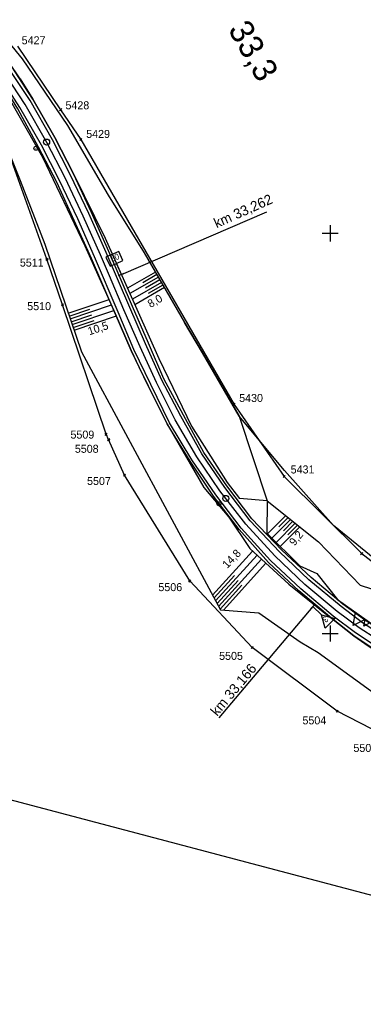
# Model space of a CAD drawing. Extents: x -805011 to -803920, y -1150790 to -1150234.
# Drawn here: x -804177.7 to -804091.7, y -1150790.1 to -1150546.6 of the extents above; entities that cross this region are included whole.
import ezdxf

# ---------------------------------------------------------------- set-up
doc = ezdxf.new("R2010")
doc.units = 0
for name, color, linetype in [('0381KM032-037P - Vrstva 1', 7, 'Continuous'), ('0381KM032-037P - Vrstva 17', 7, 'Continuous'), ('0381KM032-037P - Vrstva 4', 7, 'Continuous'), ('0381KM032-037P - Vrstva 48', 7, 'Continuous'), ('0381KM032-037P - Vrstva 49', 7, 'Continuous'), ('0381KM032-037P - Vrstva 5', 7, 'Continuous'), ('0381KM032-037P - Vrstva 50', 7, 'Continuous'), ('0381KM032-037P - Vrstva 7', 7, 'Continuous'), ('formát', 7, 'Continuous'), ('krizky_1000 - Vrstva 1', 7, 'Continuous'), ('szdc - hran DP', 7, 'Continuous'), ('szdc - szdc_cislo', 7, 'Continuous'), ('szdc - szdc_krizek', 7, 'Continuous')]:
    doc.layers.add(name, color=color, linetype=linetype)

msp = doc.modelspace()

# ---------------------------------------------------------------- linework, layer by layer
at = {"layer": '0381KM032-037P - Vrstva 1'}
for points in [[(-804170.82, -1150577.3), (-804176.26, -1150567.85), (-804182.37, -1150558.45), (-804188.8, -1150549.63), (-804195.8, -1150541.09), (-804203.2, -1150532.98), (-804210.73, -1150525.57), (-804219.76, -1150517.68), (-804222.98, -1150515.09)], [(-804121.06, -1150672.62), (-804127.59, -1150664.31), (-804133.36, -1150655.8), (-804138.71, -1150646.59), (-804143.42, -1150637.27), (-804147.52, -1150628.35), (-804151.54, -1150619.12), (-804155.16, -1150610.64), (-804157.42, -1150605.4), (-804161.72, -1150595.74), (-804166.25, -1150586.16), (-804170.82, -1150577.3)], [(-803978.41, -1150722.71), (-803983.51, -1150723.68), (-803993.92, -1150724.91), (-804004.46, -1150725.42), (-804014.95, -1150725.21), (-804025.47, -1150724.25), (-804035.41, -1150722.67), (-804044.08, -1150720.74), (-804054.77, -1150717.61), (-804064.47, -1150714.03), (-804074.16, -1150709.61), (-804083.95, -1150704.25), (-804092.73, -1150698.52), (-804098.22, -1150694.46), (-804106.33, -1150687.73), (-804113.82, -1150680.6), (-804121.06, -1150672.62)]]:
    msp.add_lwpolyline(points, dxfattribs=at)
at = {"layer": '0381KM032-037P - Vrstva 17'}
for points in [[(-804099.12, -1150672.95), (-804111.38, -1150659.24), (-804122.71, -1150645.64), (-804131.91, -1150629.82), (-804136.37, -1150622.31)], [(-804059.54, -1150698.86), (-804062.04, -1150700.07), (-804077.59, -1150690.55), (-804099.12, -1150672.95)]]:
    msp.add_lwpolyline(points, dxfattribs=at)
at = {"layer": '0381KM032-037P - Vrstva 4'}
for points in [[(-804155.96, -1150604.81), (-804160.35, -1150595.07), (-804164.87, -1150585.5), (-804169.43, -1150576.62), (-804175.01, -1150566.82), (-804181.12, -1150557.55), (-804187.68, -1150548.56)], [(-804155.31, -1150604.52), (-804159.65, -1150594.76), (-804164.13, -1150585.17), (-804168.86, -1150576.08), (-804174.28, -1150566.45), (-804180.44, -1150557.11), (-804187.11, -1150547.91)], [(-804159.67, -1150606.25), (-804163.99, -1150596.78), (-804168.29, -1150587.2), (-804172.88, -1150578.5), (-804178.08, -1150568.91), (-804181.43, -1150563.5), (-804184.18, -1150559.55), (-804190.46, -1150550.87)], [(-804158.94, -1150605.89), (-804163.07, -1150596.41), (-804167.66, -1150586.77), (-804172.11, -1150577.99), (-804177.55, -1150568.56), (-804183.56, -1150559.32), (-804190.06, -1150550.44)], [(-804132.06, -1150655.06), (-804137.36, -1150645.71), (-804142.06, -1150636.68), (-804146.12, -1150627.62), (-804150.08, -1150618.55), (-804155.96, -1150604.81)], [(-804131.6, -1150654.76), (-804136.67, -1150645.43), (-804141.53, -1150636.36), (-804145.41, -1150627.43), (-804149.44, -1150618.25), (-804155.31, -1150604.52)], [(-804135, -1150656.89), (-804140.73, -1150647.62), (-804145.48, -1150638.07), (-804149.71, -1150629.27), (-804153.71, -1150619.99), (-804159.67, -1150606.25)], [(-804134.56, -1150656.61), (-804140.15, -1150647.32), (-804144.81, -1150637.78), (-804149.09, -1150628.99), (-804152.99, -1150619.67), (-804158.94, -1150605.89)], [(-804073.38, -1150708.29), (-804083.27, -1150702.88), (-804091.89, -1150697.28), (-804097.27, -1150693.2), (-804105.34, -1150686.53), (-804112.64, -1150679.57), (-804120.03, -1150671.79), (-804126.35, -1150663.48), (-804132.06, -1150655.06)], [(-804073.1, -1150707.59), (-804077.68, -1150705.14), (-804082.78, -1150702.25), (-804091.44, -1150696.56), (-804096.83, -1150692.65), (-804104.73, -1150685.98), (-804112.1, -1150679.17), (-804119.6, -1150671.34), (-804125.86, -1150663.1), (-804131.6, -1150654.76)], [(-804075.18, -1150711.95), (-804085.34, -1150706.36), (-804094.07, -1150700.58), (-804099.68, -1150696.17), (-804107.82, -1150689.29), (-804115.4, -1150682.25), (-804122.72, -1150674.01), (-804129.15, -1150665.64), (-804135, -1150656.89)], [(-804074.79, -1150711.15), (-804084.84, -1150705.62), (-804093.69, -1150699.81), (-804099.23, -1150695.65), (-804107.33, -1150688.8), (-804114.94, -1150681.73), (-804122.23, -1150673.64), (-804128.61, -1150665.3), (-804134.56, -1150656.61)]]:
    msp.add_lwpolyline(points, dxfattribs=at)
at = {"layer": '0381KM032-037P - Vrstva 48'}
for p, q in [((-804143.67, -1150609.66), (-804150.65, -1150613.69)), ((-804142.92, -1150610.96), (-804150.03, -1150615.07)), ((-804142.17, -1150612.26), (-804149.42, -1150616.44)), ((-804143.3, -1150610.31), (-804146.82, -1150612.35)), ((-804142.55, -1150611.61), (-804146.14, -1150613.68)), ((-804141.42, -1150613.56), (-804148.81, -1150617.82)), ((-804141.8, -1150612.91), (-804145.46, -1150615.02)), ((-804165.46, -1150619.97), (-804155.27, -1150616.52)), ((-804165.22, -1150620.68), (-804160.09, -1150618.94)), ((-804164.98, -1150621.39), (-804154.65, -1150617.89)), ((-804164.5, -1150622.81), (-804154.04, -1150619.27)), ((-804164.74, -1150622.1), (-804159.54, -1150620.34)), ((-804164.26, -1150623.52), (-804158.99, -1150621.74)), ((-804164.02, -1150624.23), (-804153.43, -1150620.64)), ((-804111.08, -1150670.5), (-804115.64, -1150675.08)), ((-804109.9, -1150671.45), (-804114.57, -1150676.14)), ((-804108.72, -1150672.39), (-804113.51, -1150677.2)), ((-804110.49, -1150670.98), (-804112.8, -1150673.29)), ((-804109.31, -1150671.92), (-804111.68, -1150674.29)), ((-804108.13, -1150672.86), (-804110.56, -1150675.3)), ((-804107.54, -1150673.33), (-804112.45, -1150678.26)), ((-804129.38, -1150690.39), (-804119.38, -1150679.38)), ((-804128.63, -1150691.79), (-804118.27, -1150680.39)), ((-804127.87, -1150693.19), (-804117.16, -1150681.39)), ((-804126.68, -1150694.11), (-804116.05, -1150682.4)), ((-804129.01, -1150691.09), (-804123.91, -1150685.49)), ((-804128.25, -1150692.49), (-804122.98, -1150686.69)), ((-804127.5, -1150693.89), (-804122.05, -1150687.9))]:
    msp.add_line(p, q, dxfattribs=at)
at = {"layer": '0381KM032-037P - Vrstva 49'}
for q in [(-804122.66, -1150666.25), (-804115.86, -1150674.86)]:
    msp.add_line((-804115.71, -1150666.79), q, dxfattribs=at)
for points in [[(-804216.26, -1150515.03), (-804196.49, -1150533.54), (-804188.66, -1150542.31), (-804183.72, -1150548.22), (-804177, -1150556.4), (-804165.66, -1150573.06), (-804155.49, -1150590.5), (-804146.45, -1150604.86), (-804136.37, -1150622.31), (-804131.91, -1150629.82), (-804122.71, -1150645.64), (-804115.71, -1150666.79), (-804102.89, -1150677.06), (-804092.51, -1150687.92), (-804076.71, -1150692.97), (-804062.72, -1150701.97), (-804052.08, -1150706.52)], [(-804177.46, -1150561.39), (-804180.44, -1150557.11), (-804187.34, -1150547.5), (-804194.06, -1150539.52)], [(-804190.46, -1150550.87), (-804184.18, -1150559.55), (-804171.89, -1150581.01)], [(-804191.88, -1150555.68), (-804187.09, -1150562.15), (-804183.47, -1150572.06), (-804177.47, -1150586.83), (-804171.32, -1150602.68), (-804162.19, -1150629.63), (-804127.41, -1150694.05), (-804117.85, -1150694.76), (-804107.49, -1150702.04), (-804103.03, -1150704.73), (-804070.42, -1150728.33), (-804053.81, -1150732.63), (-804001.62, -1150732.39)], [(-804177.46, -1150561.39), (-804174.28, -1150566.45), (-804168.86, -1150576.08), (-804164.13, -1150585.17), (-804156.2, -1150601.21), (-804142.82, -1150631.28), (-804134.64, -1150648.13), (-804125.75, -1150662.22), (-804122.66, -1150666.25)], [(-804171.89, -1150581.01), (-804161.29, -1150603.14), (-804153.71, -1150619.99), (-804149.71, -1150629.27), (-804147.81, -1150633.31), (-804145.48, -1150638.07), (-804140.73, -1150647.62), (-804139.02, -1150650.67), (-804131.55, -1150663.46), (-804125.32, -1150670.91), (-804120.07, -1150678.75), (-804110.3, -1150687.62), (-804101.36, -1150694.88), (-804099.68, -1150696.17), (-804094.07, -1150700.58), (-804090.5, -1150703.01), (-804085.34, -1150706.36), (-804081.43, -1150711.18)], [(-804115.86, -1150674.86), (-804107.6, -1150683.08), (-804103.3, -1150684.96), (-804098.16, -1150691.46), (-804087.29, -1150699.16)]]:
    msp.add_lwpolyline(points, dxfattribs=at)
at = {"layer": '0381KM032-037P - Vrstva 5'}
for p, q in [((-804152.17, -1150610.26), (-804115.82, -1150594.67)), ((-804152.87, -1150610.57), (-804151.5, -1150609.96)), ((-804103.76, -1150692.66), (-804104.82, -1150693.72)), ((-804104.29, -1150693.19), (-804127.82, -1150721.03))]:
    msp.add_line(p, q, dxfattribs=at)
for points in [[(-804152.18, -1150610.26), (-804153.41, -1150607.52), (-804151.81, -1150606.81), (-804152.83, -1150604.53), (-804156.03, -1150605.96), (-804155.01, -1150608.24), (-804153.41, -1150607.52)], [(-804104.29, -1150693.19), (-804102.17, -1150695.31), (-804098.81, -1150696.19), (-804101.28, -1150698.67), (-804102.17, -1150695.31)]]:
    msp.add_lwpolyline(points, dxfattribs=at)
at = {"layer": '0381KM032-037P - Vrstva 50'}
msp.add_lwpolyline([(-804090.07, -1150697.33), (-804091.56, -1150698.09), (-804091.28, -1150696.44), (-804094.26, -1150697.96), (-804093.69, -1150694.66)], dxfattribs=at)
at = {"layer": '0381KM032-037P - Vrstva 7'}
for p, q in [((-804173.51, -1150578.79), (-804173.56, -1150578.7)), ((-804127.76, -1150667.59), (-804127.82, -1150667.51))]:
    msp.add_line(p, q, dxfattribs=at)
for centre, radius in [((-804170.87, -1150577.21), 0.75), ((-804173.53, -1150578.75), 0.5), ((-804126.09, -1150666.21), 0.75), ((-804127.79, -1150667.55), 0.5)]:
    msp.add_circle(centre, radius, dxfattribs=at)
at = {"layer": 'formát'}
msp.add_line((-803996.25, -1150790.14), (-804199.27, -1150736.42), dxfattribs=at)
at = {"layer": 'krizky_1000 - Vrstva 1'}
for points in [[(-804102, -1150600), (-804098, -1150600)], [(-804100, -1150598), (-804100, -1150602)], [(-804102, -1150700), (-804098, -1150700)], [(-804100, -1150698), (-804100, -1150702)]]:
    msp.add_lwpolyline(points, dxfattribs=at)
at = {"layer": 'szdc - hran DP'}
for p, q in [((-804178.11, -1150553.27), (-804167.37, -1150569.11)), ((-804167.37, -1150569.11), (-804162.29, -1150576.56)), ((-804170.78, -1150606.46), (-804182.55, -1150573.8)), ((-804162.29, -1150576.56), (-804123.96, -1150642.72)), ((-804166.92, -1150617.84), (-804170.78, -1150606.46)), ((-804155.97, -1150650.2), (-804166.92, -1150617.84)), ((-804123.96, -1150642.72), (-804111.51, -1150660.72)), ((-804155.38, -1150651.53), (-804155.97, -1150650.2)), ((-804151.42, -1150660.42), (-804155.38, -1150651.53)), ((-804135.09, -1150686.84), (-804151.42, -1150660.42)), ((-804111.51, -1150660.72), (-804092.1, -1150680)), ((-804092.1, -1150680), (-804079.43, -1150689.81)), ((-804119.46, -1150703.45), (-804135.09, -1150686.84)), ((-804098.25, -1150719.35), (-804119.46, -1150703.45)), ((-804086.77, -1150725.31), (-804098.25, -1150719.35))]:
    msp.add_line(p, q, dxfattribs=at)
at = {"layer": 'szdc - szdc_krizek'}
for p, q in [((-804167.1, -1150569.38), (-804167.64, -1150568.84)), ((-804167.64, -1150569.38), (-804167.1, -1150568.84)), ((-804162.03, -1150576.82), (-804162.56, -1150576.29)), ((-804162.56, -1150576.82), (-804162.03, -1150576.29)), ((-804170.52, -1150606.73), (-804171.05, -1150606.2)), ((-804171.05, -1150606.73), (-804170.52, -1150606.2)), ((-804166.66, -1150618.1), (-804167.19, -1150617.57)), ((-804167.19, -1150618.1), (-804166.66, -1150617.57)), ((-804123.7, -1150642.99), (-804124.23, -1150642.46)), ((-804124.23, -1150642.99), (-804123.7, -1150642.46)), ((-804155.71, -1150650.47), (-804156.24, -1150649.94)), ((-804156.24, -1150650.47), (-804155.71, -1150649.94)), ((-804155.11, -1150651.79), (-804155.65, -1150651.27)), ((-804155.65, -1150651.79), (-804155.11, -1150651.27)), ((-804151.16, -1150660.69), (-804151.69, -1150660.16)), ((-804151.69, -1150660.69), (-804151.16, -1150660.16)), ((-804111.24, -1150660.99), (-804111.78, -1150660.46)), ((-804111.78, -1150660.99), (-804111.24, -1150660.46)), ((-804091.83, -1150680.27), (-804092.37, -1150679.74)), ((-804092.37, -1150680.27), (-804091.83, -1150679.74)), ((-804134.83, -1150687.1), (-804135.36, -1150686.57)), ((-804135.36, -1150687.1), (-804134.83, -1150686.57)), ((-804119.2, -1150703.72), (-804119.73, -1150703.19)), ((-804119.73, -1150703.72), (-804119.2, -1150703.19)), ((-804097.98, -1150719.61), (-804098.52, -1150719.08)), ((-804098.52, -1150719.61), (-804097.98, -1150719.08))]:
    msp.add_line(p, q, dxfattribs=at)

# ---------------------------------------------------------------- texts
at = {"layer": '0381KM032-037P - Vrstva 48'}
for s, rotation, p in [('8,0', 29.9889, (-804144.91, -1150618.69)), ('10,5', 18.3536, (-804160.19, -1150625.49)), ('9,2', 51.2857, (-804108.89, -1150678.22)), ('14,8', 45.8956, (-804125.73, -1150683.84))]:
    msp.add_text(s, height=2, rotation=rotation, dxfattribs=at).set_placement(p)
at = {"layer": '0381KM032-037P - Vrstva 5'}
for s, height, rotation, p in [('km 33,262', 2.5, 24.1108, (-804128.38, -1150598.75)), ('50', 1.5, 24.1108, (-804154.55, -1150607.21)), ('3', 1.5, 225.0712, (-804101.33, -1150695.53)), ('km 33,166', 2.5, 50.0712, (-804128.22, -1150720.78))]:
    msp.add_text(s, height=height, rotation=rotation, dxfattribs=at).set_placement(p)
at = {"layer": '0381KM032-037P - Vrstva 7'}
msp.add_text('33,3', height=6, rotation=299.9223, dxfattribs=at).set_placement((-804125.64, -1150549.08))
at = {"layer": 'szdc - szdc_cislo'}
for s, p in [('5427', (-804177.11, -1150552.78)), ('5428', (-804166.16, -1150569.01)), ('5429', (-804160.98, -1150576.17)), ('5511', (-804177.56, -1150608.31)), ('5510', (-804175.72, -1150619.19)), ('5430', (-804122.74, -1150642.13)), ('5509', (-804164.91, -1150651.28)), ('5508', (-804163.82, -1150654.82)), ('5431', (-804109.87, -1150659.98)), ('5507', (-804160.76, -1150662.86)), ('5506', (-804142.93, -1150689.38)), ('5505', (-804127.75, -1150706.55)), ('5504', (-804106.92, -1150722.66)), ('5503', (-804094.18, -1150729.55))]:
    msp.add_text(s, height=2, dxfattribs=at).set_placement(p)

doc.saveas('drawing.dxf')
